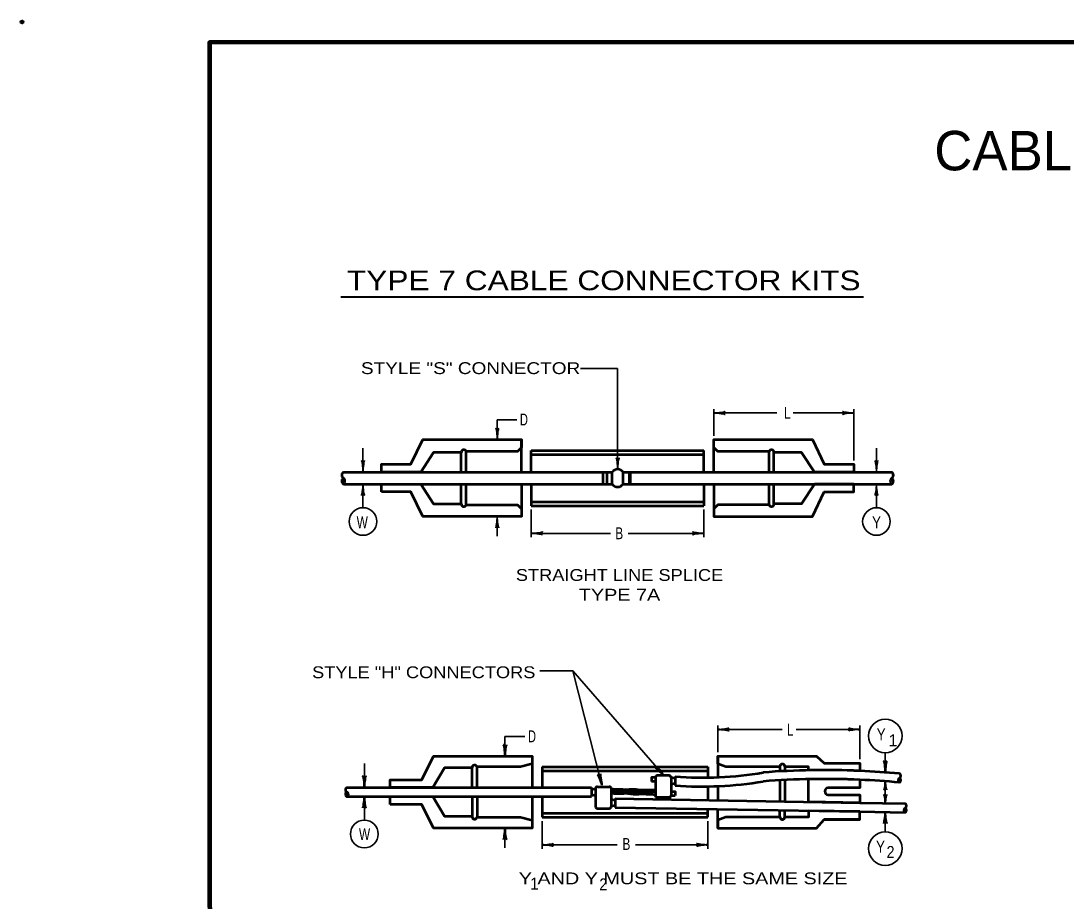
# Model space of a CAD drawing. Extents: x -8 to 705, y -12 to 442.
# Drawn here: x -8.2 to 256.6, y 218.9 to 442 of the extents above; entities that cross this region are included whole.
import ezdxf
from ezdxf.enums import TextEntityAlignment as Align

# ---------------------------------------------------------------- set-up
doc = ezdxf.new("R2010")
doc.units = 0
doc.header["$LTSCALE"] = 1.2
doc.header["$PDMODE"] = 32
doc.header["$PDSIZE"] = 0.6
doc.layers.add('1', color=7, linetype='Continuous', lineweight=53)

msp = doc.modelspace()

# ---------------------------------------------------------------- linework, layer by layer
at = {"layer": '1', "lineweight": 40}
msp.add_line((72.817, 372.085), (205.304, 372.085), dxfattribs=at)
at = {"layer": '1', "lineweight": 35}
for p, q in [((133.535, 353.897), (142.987, 353.897)), ((142.987, 328.37), (142.987, 353.897)), ((167.355, 336.889), (167.355, 343.639)), ((167.355, 342.639), (183.29, 342.639)), ((187.473, 342.639), (202.855, 342.639)), ((202.855, 330.639), (202.855, 343.639)), ((112.476, 335.885), (112.476, 340.885)), ((112.476, 340.885), (117.476, 340.885)), ((78.451, 327.722), (78.451, 333.722)), ((208.574, 327.722), (208.574, 333.722)), ((78.451, 324.639), (78.451, 318.639)), ((208.574, 324.639), (208.574, 318.639)), ((121.105, 318.139), (121.105, 311.139)), ((164.855, 318.139), (164.855, 311.139)), ((112.476, 316.389), (112.476, 311.389)), ((121.105, 312.139), (141.146, 312.139)), ((145.639, 312.139), (164.855, 312.139)), ((131.65, 277.258), (123.283, 277.258)), ((168.361, 256.687), (168.361, 263.437)), ((168.361, 262.437), (184.701, 262.437)), ((188.215, 262.437), (204.361, 262.437)), ((204.361, 254.931), (204.361, 263.437)), ((114.433, 255.687), (114.433, 260.682)), ((114.433, 260.682), (119.433, 260.682)), ((210.805, 251.552), (210.805, 256.552)), ((78.793, 247.818), (78.793, 253.818)), ((210.805, 249.302), (210.805, 243.743)), ((78.793, 245.437), (78.793, 239.437)), ((210.805, 241.493), (210.805, 236.493)), ((123.861, 239.187), (123.861, 232.187)), ((165.861, 239.187), (165.861, 232.187)), ((114.433, 237.437), (114.433, 232.437)), ((123.861, 233.187), (142.863, 233.187)), ((147.549, 233.187), (165.861, 233.187))]:
    msp.add_line(p, q, dxfattribs=at)
at = {"layer": '1'}
for p, q in [((118.605, 327.639), (118.605, 335.889)), ((167.355, 327.639), (167.355, 335.889)), ((192.355, 335.889), (195.355, 329.639)), ((103.355, 327.639), (103.355, 332.639)), ((104.605, 327.639), (104.605, 332.889)), ((121.105, 327.639), (121.105, 333.139)), ((121.105, 333.139), (164.855, 333.139)), ((121.105, 332.139), (164.855, 332.139)), ((164.855, 327.639), (164.855, 333.139)), ((181.355, 327.639), (181.355, 332.889)), ((182.605, 327.639), (182.605, 332.639)), ((139.355, 324.639), (139.355, 327.639)), ((140.355, 324.639), (140.355, 327.639)), ((141.605, 324.639), (141.605, 327.639)), ((144.355, 324.639), (144.355, 327.639)), ((103.355, 319.639), (103.355, 324.639)), ((104.605, 319.389), (104.605, 324.639)), ((118.605, 324.639), (118.605, 316.389)), ((121.105, 324.639), (121.105, 319.139)), ((144.355, 324.639), (202.855, 324.639)), ((164.855, 324.639), (164.855, 319.139)), ((167.355, 324.639), (167.355, 316.389)), ((181.355, 319.389), (181.355, 324.639)), ((182.605, 319.639), (182.605, 324.639)), ((202.855, 324.639), (212.48, 324.639)), ((93.605, 316.389), (90.605, 322.639)), ((192.355, 316.389), (195.355, 322.639)), ((121.105, 320.139), (164.855, 320.139)), ((121.105, 319.139), (164.855, 319.139)), ((121.361, 255.687), (121.361, 247.687)), ((168.361, 255.687), (168.361, 250.513)), ((168.361, 255.687), (193.361, 255.687)), ((193.361, 255.687), (195.361, 253.931)), ((106.111, 247.687), (106.111, 252.687)), ((107.361, 247.687), (107.361, 252.937)), ((123.861, 252.937), (123.861, 247.687)), ((123.861, 252.937), (165.861, 252.937)), ((123.861, 251.937), (165.861, 251.937)), ((165.861, 252.937), (165.861, 250.425)), ((184.111, 252.937), (184.111, 251.811)), ((185.361, 252.937), (185.361, 251.876)), ((152.538, 249.228), (151.538, 249.228)), ((152.538, 250.228), (152.538, 245.728)), ((156.038, 250.728), (153.038, 250.728)), ((156.538, 250.228), (156.538, 245.728)), ((157.538, 249.978), (156.538, 250.228)), ((157.538, 250.478), (157.538, 248.228)), ((184.111, 249.561), (184.111, 244.209)), ((185.361, 249.626), (185.361, 244.187)), ((191.361, 244.082), (191.361, 249.833)), ((136.361, 247.687), (136.361, 245.437)), ((136.361, 247.187), (137.361, 247.437)), ((137.361, 247.437), (137.361, 242.937)), ((137.861, 247.937), (140.861, 247.937)), ((141.361, 247.437), (141.361, 242.937)), ((157.538, 248.728), (156.538, 248.478)), ((165.861, 248.175), (165.861, 244.527)), ((168.361, 248.263), (168.361, 244.483)), ((106.111, 245.437), (106.111, 240.437)), ((107.361, 245.437), (107.361, 240.187)), ((121.361, 245.437), (121.361, 237.437)), ((123.861, 245.437), (123.861, 240.187)), ((136.361, 245.937), (137.361, 245.687)), ((142.361, 244.437), (141.361, 244.687)), ((142.361, 244.937), (142.361, 242.687)), ((142.361, 244.937), (204.361, 243.855)), ((156.038, 245.228), (153.038, 245.228)), ((156.538, 245.728), (157.538, 245.728)), ((204.361, 243.855), (215.85, 243.655)), ((123.861, 241.187), (165.861, 241.187)), ((137.861, 242.437), (140.861, 242.437)), ((142.361, 243.187), (141.361, 242.937)), ((142.361, 242.687), (204.361, 241.605)), ((165.861, 240.187), (165.861, 242.277)), ((168.361, 237.437), (168.361, 242.233)), ((184.111, 240.187), (184.111, 241.959)), ((185.361, 240.187), (185.361, 241.937)), ((204.361, 241.605), (191.361, 241.832)), ((204.361, 241.605), (215.85, 241.405)), ((123.861, 240.187), (165.861, 240.187)), ((204.361, 239.605), (195.361, 239.605))]:
    msp.add_line(p, q, dxfattribs=at)
at = {"layer": '1', "lineweight": 70}
msp.add_line((146.105, 324.639), (146.105, 327.639), dxfattribs=at)
at = {"layer": '1', "lineweight": 158}
msp.add_lwpolyline([(699.308, 436.624), (39.557, 436.541), (39.641, -1.793)], dxfattribs=at)
at = {"layer": '1'}
for points in [[(83.105, 327.639), (83.105, 329.639), (90.605, 329.639), (93.605, 335.889), (118.605, 335.889), (118.605, 333.889), (117.605, 332.889), (104.605, 332.889)], [(167.355, 333.889), (167.355, 335.889), (192.355, 335.889), (195.355, 329.639), (202.855, 329.639), (202.855, 327.639), (192.855, 327.639), (189.605, 332.639), (182.605, 332.639)], [(181.355, 332.889), (168.355, 332.889), (167.355, 333.889)], [(103.355, 332.639), (96.355, 332.639), (93.105, 327.639), (83.105, 327.639)], [(73.48, 327.639), (83.105, 327.639), (118.605, 327.639), (141.605, 327.639)], [(144.355, 327.639), (202.855, 327.639), (212.48, 327.639)], [(73.48, 324.639), (83.105, 324.639), (118.605, 324.639), (141.605, 324.639)], [(83.105, 322.639), (83.105, 324.639), (93.105, 324.639), (96.355, 319.639), (103.355, 319.639)], [(167.355, 318.389), (167.355, 316.389), (192.355, 316.389), (195.355, 322.639), (202.855, 322.639), (202.855, 324.639), (192.855, 324.639), (189.605, 319.639), (182.605, 319.639)], [(104.605, 319.389), (117.605, 319.389), (118.605, 318.389), (118.605, 316.389), (93.605, 316.389), (90.605, 322.639), (83.105, 322.639)], [(181.355, 319.389), (168.355, 319.389), (167.355, 318.389)], [(85.361, 247.687), (85.361, 249.687), (93.361, 249.687), (96.361, 255.687), (121.361, 255.687), (121.361, 253.687), (118.361, 252.937), (107.361, 252.937)], [(168.361, 253.687), (168.361, 255.687), (193.361, 255.687), (195.361, 253.931), (204.361, 253.931), (204.361, 251.931)], [(106.111, 252.687), (99.111, 252.687), (96.111, 247.687), (85.361, 247.687)], [(184.111, 252.937), (170.361, 252.937), (168.361, 253.687)], [(191.361, 252.083), (191.361, 252.937), (185.361, 252.937)], [(152.538, 250.228), (151.538, 250.228), (151.538, 249.228)], [(204.361, 249.681), (204.361, 247.681), (196.361, 247.681)], [(74.361, 247.687), (85.361, 247.687), (136.361, 247.687)], [(156.538, 246.728), (157.538, 246.728), (157.538, 245.728)], [(74.361, 245.437), (85.361, 245.437), (136.361, 245.437)], [(85.361, 243.437), (85.361, 245.437), (96.111, 245.437), (99.111, 240.437), (106.111, 240.437)], [(196.361, 245.855), (204.361, 245.855), (204.361, 243.855), (191.361, 244.082)], [(107.361, 240.187), (118.361, 240.187), (121.361, 239.437), (121.361, 237.437), (96.361, 237.437), (93.361, 243.437), (85.361, 243.437)], [(184.111, 240.187), (170.361, 240.187), (168.361, 239.437), (168.361, 237.437), (193.361, 237.437), (195.361, 239.605), (204.361, 239.605), (204.361, 241.605)], [(191.361, 241.832), (191.361, 240.187), (185.361, 240.187)]]:
    msp.add_lwpolyline(points, dxfattribs=at)
at = {"layer": '1', "lineweight": 35}
msp.add_lwpolyline([(139.014, 248.297), (131.65, 277.258), (154.691, 250.728)], dxfattribs=at)
for centre, radius in [((78.451, 315.139), 3.5), ((208.574, 315.139), 3.5), ((210.805, 260.802), 4.25), ((78.793, 235.937), 3.5), ((210.805, 232.243), 4.25)]:
    msp.add_circle(centre, radius, dxfattribs=at)
at = {"layer": '1'}
for centre, radius, start, end in [((103.993, 332.7), 0.641, 17.19718, 185.42268), ((103.993, 332.697), 0.641, 17.4811, 185.13877), ((181.967, 332.7), 0.641, 354.57732, 162.80282), ((181.966, 332.695), 0.641, 355.01091, 162.36922), ((74.001, 326.889), 0.913, 124.81412, 235.18588), ((74.001, 325.389), 0.913, 124.81412, 235.18588), ((72.969, 325.389), 0.913, 304.81412, 55.18588), ((142.98, 326.711), 1.659, 34.01504, 145.98495), ((212.99, 325.389), 0.913, 124.81412, 235.18588), ((211.958, 326.889), 0.913, 304.81412, 55.18588), ((211.958, 325.389), 0.913, 304.81412, 55.18588), ((142.98, 325.567), 1.659, 214.01505, 325.98496), ((103.993, 319.579), 0.641, 174.57732, 342.80282), ((103.993, 319.582), 0.641, 174.90411, 342.47603), ((181.966, 319.582), 0.641, 197.46332, 5.15654), ((181.967, 319.579), 0.641, 197.19718, 5.42268), ((106.745, 252.768), 0.639, 15.34061, 187.27926), ((106.749, 252.745), 0.641, 17.49094, 185.12892), ((195.461, 45.851), 206.273, 87.52703, 94.33724), ((184.736, 253.04), 0.633, 350.65579, 189.34422), ((184.736, 253.031), 0.632, 351.47717, 188.52283), ((195.461, 45.851), 206.273, 87.52704, 91.13885), ((195.461, 45.851), 206.273, 84.72683, 87.52704), ((153.038, 250.228), 0.5, 90, 180), ((156.038, 250.228), 0.5, 0, 90), ((164.294, 344.261), 94.025, 265.87965, 279.52988), ((164.294, 342.011), 94.025, 265.87965, 279.52988), ((195.461, 43.601), 206.273, 87.52703, 94.33724), ((195.461, 43.601), 206.273, 87.52704, 91.13885), ((195.461, 43.601), 206.273, 84.72683, 87.52704), ((214.717, 249.563), 0.639, 118.32317, 241.67683), ((214.115, 250.688), 0.639, 298.32317, 61.67683), ((214.115, 249.563), 0.639, 298.32317, 61.67683), ((74.579, 247.125), 0.603, 111.19742, 248.80258), ((74.579, 246), 0.603, 111.19742, 248.80258), ((74.143, 246), 0.603, 291.19742, 68.80258), ((137.861, 247.437), 0.5, 90, 180), ((140.861, 247.437), 0.5, 0, 90), ((196.441, 246.768), 0.917, 94.99721, 265.00279), ((153.038, 245.728), 0.5, 180, 270), ((156.038, 245.728), 0.5, 270, 0), ((137.861, 242.937), 0.5, 180, 270), ((140.861, 242.937), 0.5, 270, 0), ((216.149, 241.967), 0.639, 118.32317, 241.67683), ((215.546, 243.092), 0.639, 298.32317, 61.67683), ((215.546, 241.967), 0.639, 298.32317, 61.67683), ((106.745, 240.356), 0.639, 172.72074, 344.65939), ((106.751, 240.387), 0.642, 175.53288, 341.84726), ((184.736, 240.29), 0.633, 170.65578, 9.34421), ((184.736, 240.21), 0.625, 182.03968, 357.96032)]:
    msp.add_arc(centre, radius, start, end, dxfattribs=at)
at = {"layer": '1', "lineweight": 35}
for centre, major_axis, ratio, start_param, end_param in [((168.475, 342.428), (-1.756, 0.176), 0.07063, 3.1407148, 5.41811), ((168.446, 342.916), (-1.786, -0.156), 0.122415, 0.8963533, 3.1415927), ((201.764, 342.363), (1.786, 0.156), 0.122415, 0.8963533, 3.1415927), ((201.734, 342.851), (1.756, -0.176), 0.07063, 3.1407148, 5.41811), ((112.199, 336.976), (0.156, -1.786), 0.122415, 0.8963533, 3.1415927), ((112.687, 337.005), (-0.176, -1.756), 0.07063, 3.1407148, 5.41811), ((142.71, 329.461), (0.156, -1.786), 0.122415, 0.8963533, 3.1415927), ((143.198, 329.491), (-0.176, -1.756), 0.07063, 3.1407148, 5.41811), ((78.175, 328.813), (0.156, -1.786), 0.122415, 0.8963533, 3.1415927), ((78.175, 328.813), (0.156, -1.786), 0.122415, 0.8963533, 3.1415927), ((78.663, 328.842), (-0.176, -1.756), 0.07063, 3.1407148, 5.41811), ((78.663, 328.842), (-0.176, -1.756), 0.07063, 3.1407148, 5.41811), ((208.298, 328.813), (0.156, -1.786), 0.122415, 0.8963533, 3.1415927), ((208.298, 328.813), (0.156, -1.786), 0.122415, 0.8963533, 3.1415927), ((208.786, 328.842), (-0.176, -1.756), 0.07063, 3.1407148, 5.41811), ((208.786, 328.842), (-0.176, -1.756), 0.07063, 3.1407148, 5.41811), ((78.24, 323.519), (0.176, 1.756), 0.07063, 3.1407148, 5.41811), ((78.728, 323.548), (-0.156, 1.786), 0.122415, 0.8963533, 3.1415927), ((208.362, 323.519), (0.176, 1.756), 0.07063, 3.1407148, 5.41811), ((208.85, 323.548), (-0.156, 1.786), 0.122415, 0.8963533, 3.1415927), ((112.264, 315.269), (0.176, 1.756), 0.07063, 3.1407148, 5.41811), ((112.752, 315.298), (-0.156, 1.786), 0.122415, 0.8963533, 3.1415927), ((122.196, 312.416), (-1.786, -0.156), 0.122415, 0.8963533, 3.1415927), ((122.225, 311.928), (-1.756, 0.176), 0.07063, 3.1407148, 5.41811), ((163.764, 311.863), (1.786, 0.156), 0.122415, 0.8963533, 3.1415927), ((163.734, 312.351), (1.756, -0.176), 0.07063, 3.1407148, 5.41811)]:
    msp.add_ellipse(centre, major_axis=major_axis, ratio=ratio, start_param=start_param, end_param=end_param, dxfattribs=at)
at = {"layer": '1', "lineweight": 40}
for centre, major_axis, ratio, start_param, end_param in [((169.481, 262.226), (-1.756, 0.176), 0.07063, 3.1407148, 5.41811), ((169.481, 262.226), (-1.756, 0.176), 0.07063, 3.1407148, 5.41811), ((169.452, 262.714), (-1.786, -0.156), 0.122415, 0.8963533, 3.1415927), ((169.452, 262.714), (-1.786, -0.156), 0.122415, 0.8963533, 3.1415927), ((203.27, 262.161), (1.786, 0.156), 0.122415, 0.8963533, 3.1415927), ((203.24, 262.649), (1.756, -0.176), 0.07063, 3.1407148, 5.41811), ((114.157, 256.779), (0.156, -1.786), 0.122415, 0.8963533, 3.1415927), ((114.645, 256.808), (-0.176, -1.756), 0.07063, 3.1407148, 5.41811), ((210.528, 252.643), (0.156, -1.786), 0.122415, 0.8963533, 3.1415927), ((210.528, 252.643), (0.156, -1.786), 0.122415, 0.8963533, 3.1415927), ((211.016, 252.673), (-0.176, -1.756), 0.07063, 3.1407148, 5.41811), ((211.016, 252.673), (-0.176, -1.756), 0.07063, 3.1407148, 5.41811), ((153.767, 251.371), (1.289, -1.246), 0.122415, 0.8963533, 3.1415927), ((154.116, 251.713), (1.019, -1.441), 0.07063, 3.1407148, 5.41811), ((78.517, 248.909), (0.156, -1.786), 0.122415, 0.8963533, 3.1415927), ((78.517, 248.909), (0.156, -1.786), 0.122415, 0.8963533, 3.1415927), ((79.005, 248.938), (-0.176, -1.756), 0.07063, 3.1407148, 5.41811), ((79.005, 248.938), (-0.176, -1.756), 0.07063, 3.1407148, 5.41811), ((138.477, 249.286), (0.591, -1.692), 0.122415, 0.8963533, 3.1415927), ((138.477, 249.286), (0.591, -1.692), 0.122415, 0.8963533, 3.1415927), ((138.943, 249.435), (-0.263, 1.746), 0.07063, 6.2823074, 8.5597026), ((138.943, 249.435), (-0.263, 1.746), 0.07063, 6.2823074, 8.5597026), ((210.537, 248.202), (0.156, 1.786), 0.122415, 4.7362681, 5.386832), ((211.073, 248.202), (-0.156, 1.786), 0.122415, 0.8963533, 1.5469172), ((210.612, 248.889), (0.156, 1.786), 0.122415, 3.1415927, 4.3421266), ((210.998, 248.889), (-0.156, 1.786), 0.122415, 1.9410587, 3.1415927), ((78.582, 244.317), (0.176, 1.756), 0.07063, 3.1407148, 5.41811), ((79.07, 244.346), (-0.156, 1.786), 0.122415, 0.8963533, 3.1415927), ((210.612, 244.155), (0.156, -1.786), 0.122415, 1.9410587, 3.1415927), ((210.537, 244.843), (0.156, -1.786), 0.122415, 0.8963533, 1.5469172), ((211.073, 244.843), (-0.156, -1.786), 0.122415, 4.7362681, 5.386832), ((210.998, 244.155), (-0.156, -1.786), 0.122415, 3.1415927, 4.3421266), ((210.593, 240.372), (0.176, 1.756), 0.07063, 3.1407148, 5.41811), ((210.593, 240.372), (0.176, 1.756), 0.07063, 3.1407148, 5.41811), ((211.081, 240.401), (-0.156, 1.786), 0.122415, 0.8963533, 3.1415927), ((211.081, 240.401), (-0.156, 1.786), 0.122415, 0.8963533, 3.1415927), ((114.222, 236.317), (0.176, 1.756), 0.07063, 3.1407148, 5.41811), ((114.709, 236.346), (-0.156, 1.786), 0.122415, 0.8963533, 3.1415927), ((124.981, 232.976), (-1.756, 0.176), 0.07063, 3.1407148, 5.41811), ((124.981, 232.976), (-1.756, 0.176), 0.07063, 3.1407148, 5.41811), ((124.952, 233.464), (-1.786, -0.156), 0.122415, 0.8963533, 3.1415927), ((124.952, 233.464), (-1.786, -0.156), 0.122415, 0.8963533, 3.1415927), ((164.77, 232.911), (1.786, 0.156), 0.122415, 0.8963533, 3.1415927), ((164.74, 233.399), (1.756, -0.176), 0.07063, 3.1407148, 5.41811)]:
    msp.add_ellipse(centre, major_axis=major_axis, ratio=ratio, start_param=start_param, end_param=end_param, dxfattribs=at)
at = {"layer": '1'}
for points in [[(141.361, 247.437), (143.031, 247.27), (144.18, 247.27), (145.247, 247.188), (146.19, 247.312), (147.052, 247.27), (147.626, 247.27), (148.611, 247.147), (149.267, 247.147), (149.965, 247.106), (150.457, 247.147), (151.401, 247.106), (152.509, 247.147)], [(141.39, 246.86), (142.744, 246.819), (143.729, 246.737), (145.001, 246.696), (145.821, 246.655), (146.929, 246.655), (148.529, 246.614), (149.883, 246.532), (150.868, 246.614), (151.934, 246.696), (152.427, 246.696)], [(152.538, 245.728), (151.893, 245.916), (150.991, 245.916), (150.047, 245.998), (148.488, 245.998), (147.544, 245.957), (146.519, 246.039), (145.657, 246.162), (144.098, 246.121), (143.072, 246.121), (142.088, 246.162), (141.431, 246.244)]]:
    msp.add_spline(points, degree=3, dxfattribs=at)
msp.add_point((-7.942, 441.707), dxfattribs=at)

# ---------------------------------------------------------------- texts
for s, height, p in [('CABLE CONNECTOR KITS', 10, (223.228, 404.13)), ('1', 3, (211.644, 258.187)), ('1', 3, (120.772, 221.86))]:
    msp.add_text(s, height=height, dxfattribs=at).set_placement(p)
for s, height, width, p in [('TYPE 7 CABLE CONNECTOR KITS', 5, 1.2, (74.367, 373.75)), ('STYLE "S" CONNECTOR', 3, 1.2, (77.93, 352.501)), ('D', 3, 0.7, (118.215, 339.482)), ('L', 3, 0.75, (185.149, 341.186)), ('W', 3, 0.75, (76.846, 313.443)), ('Y', 3, 0.85, (207.461, 313.443)), ('B', 3, 0.75, (142.386, 310.653)), ('STYLE "H" CONNECTORS', 3, 1.15, (65.546, 275.43)), ('L', 3, 0.75, (185.872, 260.866)), ('Y', 3, 0.85, (208.632, 259.694)), ('D', 3, 0.7, (120.27, 259.192)), ('W', 3, 0.75, (77.428, 234.416)), ('B', 3, 0.75, (144.202, 231.904)), ('Y', 3, 0.85, (208.465, 231.235)), ('2', 3, 0.9, (211.142, 229.896)), ('Y AND Y MUST BE THE SAME SIZE', 3, 1.25, (117.927, 223.199)), ('2', 3, 0.9, (138.344, 221.693))]:
    msp.add_text(s, height=height, dxfattribs=dict(at, width=width)).set_placement(p)
for s, width, p in [('STRAIGHT LINE SPLICE', 1.15, (143.47, 300.084)), ('TYPE 7A', 1.25, (143.47, 295.084))]:
    msp.add_text(s, height=3, dxfattribs=dict(at, width=width)).set_placement(p, align=Align.CENTER)

doc.saveas('drawing.dxf')
